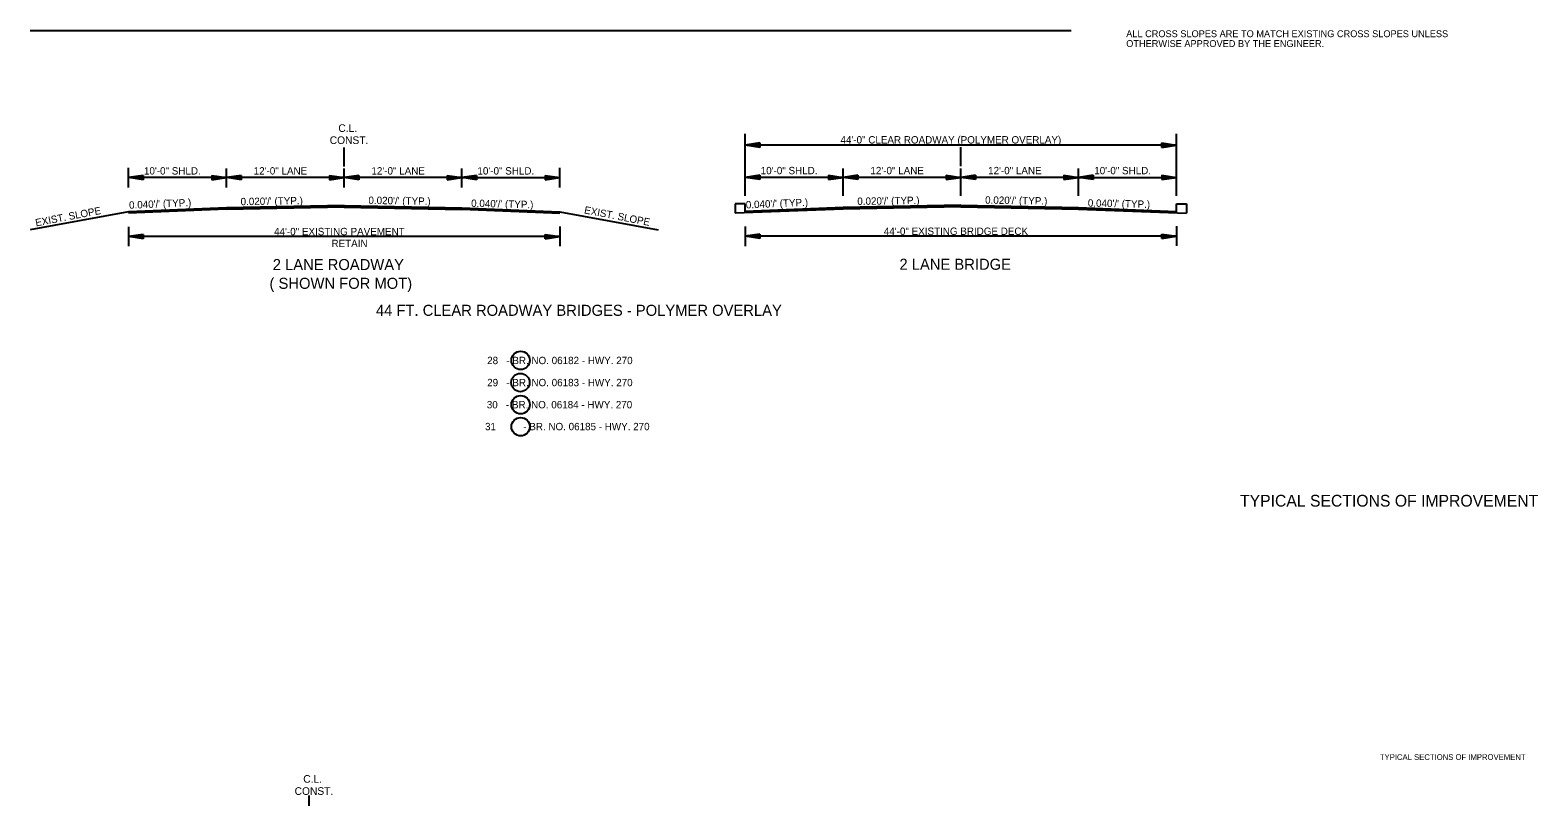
# Model space of a CAD drawing. Extents: x 550980 to 1930787, y -1972975 to 596640.
# Drawn here: x 551009 to 552546, y -1959487 to -1958697 of the extents above; entities that cross this region are included whole.
import ezdxf

# ---------------------------------------------------------------- set-up
doc = ezdxf.new("R2010")
doc.units = 0
for name, color, linetype in [('R_Border', 7, 'Continuous'), ('R_Border Notes', 7, 'Continuous'), ('R_Draft', 7, 'Continuous'), ('S_AREA_CALC', 7, 'Continuous')]:
    doc.layers.add(name, color=color, linetype=linetype)

msp = doc.modelspace()

# ---------------------------------------------------------------- linework, layer by layer
at = {"layer": 'R_Border'}
for p, q in [((551009, -1958697.2), (552070.2, -1958697.2)), ((551737.7, -1958873.9), (551727.5, -1958873.9)), ((551727.5, -1958873.9), (551727.5, -1958883.4)), ((551737.7, -1958882.7), (551737.7, -1958873.9)), ((552177.7, -1958882.7), (552177.7, -1958873.9)), ((552177.7, -1958873.9), (552187.9, -1958873.9)), ((552187.9, -1958873.9), (552187.8, -1958883.4))]:
    msp.add_line(p, q, dxfattribs=at)
for centre in [(551508.9, -1959033.2), (551508.7, -1959055.7), (551508.9, -1959078.3), (551508.9, -1959100.7)]:
    msp.add_circle(centre, 9.34, dxfattribs=at)
at = {"layer": 'R_Draft'}
for p, q in [((551737.7, -1958865.6), (551737.7, -1958802.5)), ((552177.7, -1958865.6), (552177.7, -1958802.5)), ((551329, -1958827.7), (551329, -1958816.3)), ((551752.7, -1958811.7), (551737.7, -1958814)), ((552177.7, -1958814), (551737.7, -1958814)), ((551752.7, -1958816.2), (551737.7, -1958814)), ((551752.7, -1958812.1), (551740.2, -1958814)), ((551752.7, -1958815.8), (551740.2, -1958814)), ((551752.7, -1958812.5), (551742.8, -1958814)), ((551752.7, -1958815.5), (551742.8, -1958814)), ((551752.7, -1958812.8), (551745.3, -1958814)), ((551752.7, -1958815.1), (551745.3, -1958814)), ((551752.7, -1958813.2), (551747.8, -1958814)), ((551752.7, -1958814.7), (551747.8, -1958814)), ((551752.7, -1958813.6), (551750.3, -1958814)), ((551752.7, -1958814.3), (551750.3, -1958814)), ((551752.7, -1958811.7), (551752.7, -1958816.2)), ((551957.7, -1958827.5), (551957.7, -1958816)), ((552162.7, -1958811.7), (552177.7, -1958814)), ((552162.7, -1958816.2), (552162.7, -1958811.7)), ((552162.7, -1958812.1), (552175.2, -1958814)), ((552162.7, -1958812.5), (552172.6, -1958814)), ((552162.7, -1958812.8), (552170.1, -1958814)), ((552162.7, -1958813.2), (552167.6, -1958814)), ((552162.7, -1958813.6), (552165.1, -1958814)), ((552162.7, -1958816.2), (552177.7, -1958814)), ((552162.7, -1958814.7), (552167.6, -1958814)), ((552162.7, -1958815.5), (552172.6, -1958814)), ((552162.7, -1958815.8), (552175.2, -1958814)), ((552162.7, -1958815.1), (552170.1, -1958814)), ((552162.7, -1958814.3), (552165.1, -1958814)), ((551109, -1958857), (551109, -1958837)), ((551209, -1958857), (551209, -1958837.9)), ((551329, -1958835.7), (551329, -1958827.7)), ((551329, -1958857), (551329, -1958837.9)), ((551449, -1958857), (551449, -1958837.9)), ((551549, -1958857), (551549, -1958837)), ((551837.7, -1958865.6), (551837.7, -1958837.6)), ((551957.7, -1958835.5), (551957.7, -1958827.5)), ((551957.7, -1958865.6), (551957.7, -1958837.6)), ((552077.7, -1958865.6), (552077.7, -1958837.6)), ((551124, -1958844.8), (551109, -1958847)), ((551209, -1958847), (551109, -1958847)), ((551124, -1958849.3), (551109, -1958847)), ((551124, -1958845.2), (551111.5, -1958847)), ((551124, -1958848.9), (551111.5, -1958847)), ((551124, -1958845.6), (551114, -1958847)), ((551124, -1958848.5), (551114, -1958847)), ((551124, -1958845.9), (551116.5, -1958847)), ((551124, -1958848.2), (551116.5, -1958847)), ((551124, -1958846.3), (551119.1, -1958847)), ((551124, -1958847.8), (551119.1, -1958847)), ((551124, -1958846.7), (551121.6, -1958847)), ((551124, -1958847.4), (551121.6, -1958847)), ((551124, -1958844.8), (551124, -1958849.3)), ((551194, -1958844.8), (551209, -1958847)), ((551194, -1958844.8), (551194, -1958849.3)), ((551194, -1958845.2), (551206.4, -1958847)), ((551194, -1958845.6), (551203.9, -1958847)), ((551194, -1958845.9), (551201.4, -1958847)), ((551194, -1958846.3), (551198.8, -1958847)), ((551194, -1958846.7), (551196.3, -1958847)), ((551194, -1958849.3), (551209, -1958847)), ((551194, -1958847.8), (551198.8, -1958847)), ((551194, -1958848.5), (551203.9, -1958847)), ((551194, -1958848.9), (551206.4, -1958847)), ((551194, -1958848.2), (551201.4, -1958847)), ((551194, -1958847.4), (551196.3, -1958847)), ((551224, -1958844.8), (551209, -1958847)), ((551329, -1958847), (551209, -1958847)), ((551224, -1958849.3), (551209, -1958847)), ((551224, -1958845.2), (551211.5, -1958847)), ((551224, -1958848.9), (551211.5, -1958847)), ((551224, -1958845.6), (551214, -1958847)), ((551224, -1958848.5), (551214, -1958847)), ((551224, -1958845.9), (551216.5, -1958847)), ((551224, -1958848.2), (551216.5, -1958847)), ((551224, -1958846.3), (551219.1, -1958847)), ((551224, -1958847.8), (551219.1, -1958847)), ((551224, -1958846.7), (551221.6, -1958847)), ((551224, -1958847.4), (551221.6, -1958847)), ((551224, -1958844.8), (551224, -1958849.3)), ((551314, -1958844.8), (551329, -1958847)), ((551314, -1958844.8), (551314, -1958849.3)), ((551314, -1958845.2), (551326.4, -1958847)), ((551314, -1958845.6), (551323.9, -1958847)), ((551314, -1958845.9), (551321.4, -1958847)), ((551314, -1958846.3), (551318.8, -1958847)), ((551314, -1958846.7), (551316.3, -1958847)), ((551314, -1958849.3), (551329, -1958847)), ((551314, -1958847.8), (551318.8, -1958847)), ((551314, -1958848.5), (551323.9, -1958847)), ((551314, -1958848.9), (551326.4, -1958847)), ((551314, -1958848.2), (551321.4, -1958847)), ((551314, -1958847.4), (551316.3, -1958847)), ((551344, -1958844.8), (551329, -1958847)), ((551449, -1958847), (551329, -1958847)), ((551344, -1958849.3), (551329, -1958847)), ((551344, -1958845.2), (551331.5, -1958847)), ((551344, -1958848.9), (551331.5, -1958847)), ((551344, -1958845.6), (551334, -1958847)), ((551344, -1958848.5), (551334, -1958847)), ((551344, -1958845.9), (551336.5, -1958847)), ((551344, -1958848.2), (551336.5, -1958847)), ((551344, -1958846.3), (551339.1, -1958847)), ((551344, -1958847.8), (551339.1, -1958847)), ((551344, -1958846.7), (551341.6, -1958847)), ((551344, -1958847.4), (551341.6, -1958847)), ((551344, -1958844.8), (551344, -1958849.3)), ((551434, -1958844.8), (551449, -1958847)), ((551434, -1958844.8), (551434, -1958849.3)), ((551434, -1958845.2), (551446.4, -1958847)), ((551434, -1958845.6), (551443.9, -1958847)), ((551434, -1958845.9), (551441.4, -1958847)), ((551434, -1958846.3), (551438.8, -1958847)), ((551434, -1958846.7), (551436.3, -1958847)), ((551434, -1958849.3), (551449, -1958847)), ((551434, -1958847.8), (551438.8, -1958847)), ((551434, -1958848.5), (551443.9, -1958847)), ((551434, -1958848.9), (551446.4, -1958847)), ((551434, -1958848.2), (551441.4, -1958847)), ((551434, -1958847.4), (551436.3, -1958847)), ((551464, -1958844.8), (551449, -1958847)), ((551449, -1958847), (551549, -1958847)), ((551464, -1958849.3), (551449, -1958847)), ((551464, -1958845.2), (551451.5, -1958847)), ((551464, -1958848.9), (551451.5, -1958847)), ((551464, -1958845.6), (551454, -1958847)), ((551464, -1958848.5), (551454, -1958847)), ((551464, -1958845.9), (551456.5, -1958847)), ((551464, -1958848.2), (551456.5, -1958847)), ((551464, -1958846.3), (551459.1, -1958847)), ((551464, -1958847.8), (551459.1, -1958847)), ((551464, -1958846.7), (551461.6, -1958847)), ((551464, -1958847.4), (551461.6, -1958847)), ((551464, -1958844.8), (551464, -1958849.3)), ((551534, -1958844.8), (551549, -1958847)), ((551534, -1958844.8), (551534, -1958849.3)), ((551534, -1958845.2), (551546.4, -1958847)), ((551534, -1958845.6), (551543.9, -1958847)), ((551534, -1958845.9), (551541.4, -1958847)), ((551534, -1958846.3), (551538.8, -1958847)), ((551534, -1958846.7), (551536.3, -1958847)), ((551534, -1958849.3), (551549, -1958847)), ((551534, -1958847.8), (551538.8, -1958847)), ((551534, -1958848.5), (551543.9, -1958847)), ((551534, -1958848.9), (551546.4, -1958847)), ((551534, -1958848.2), (551541.4, -1958847)), ((551534, -1958847.4), (551536.3, -1958847)), ((551752.7, -1958844.5), (551737.7, -1958846.8)), ((551837.7, -1958846.8), (551737.7, -1958846.8)), ((551752.7, -1958849), (551737.7, -1958846.8)), ((551752.7, -1958844.9), (551740.2, -1958846.8)), ((551752.7, -1958848.7), (551740.2, -1958846.8)), ((551752.7, -1958845.3), (551742.8, -1958846.8)), ((551752.7, -1958848.3), (551742.8, -1958846.8)), ((551752.7, -1958845.7), (551745.3, -1958846.8)), ((551752.7, -1958847.9), (551745.3, -1958846.8)), ((551752.7, -1958846.1), (551747.8, -1958846.8)), ((551752.7, -1958847.5), (551747.8, -1958846.8)), ((551752.7, -1958846.4), (551750.3, -1958846.8)), ((551752.7, -1958847.2), (551750.3, -1958846.8)), ((551752.7, -1958844.5), (551752.7, -1958849)), ((551822.7, -1958844.5), (551837.7, -1958846.8)), ((551822.7, -1958844.5), (551822.7, -1958849)), ((551822.7, -1958844.9), (551835.2, -1958846.8)), ((551822.7, -1958845.3), (551832.6, -1958846.8)), ((551822.7, -1958845.7), (551830.1, -1958846.8)), ((551822.7, -1958846.1), (551827.6, -1958846.8)), ((551822.7, -1958846.4), (551825.1, -1958846.8)), ((551822.7, -1958849), (551837.7, -1958846.8)), ((551822.7, -1958847.5), (551827.6, -1958846.8)), ((551822.7, -1958848.3), (551832.6, -1958846.8)), ((551822.7, -1958848.7), (551835.2, -1958846.8)), ((551822.7, -1958847.9), (551830.1, -1958846.8)), ((551822.7, -1958847.2), (551825.1, -1958846.8)), ((551852.7, -1958844.5), (551837.7, -1958846.8)), ((551957.7, -1958846.8), (551837.7, -1958846.8)), ((551852.7, -1958849), (551837.7, -1958846.8)), ((551852.7, -1958844.9), (551840.2, -1958846.8)), ((551852.7, -1958848.7), (551840.2, -1958846.8)), ((551852.7, -1958845.3), (551842.8, -1958846.8)), ((551852.7, -1958848.3), (551842.8, -1958846.8)), ((551852.7, -1958845.7), (551845.3, -1958846.8)), ((551852.7, -1958847.9), (551845.3, -1958846.8)), ((551852.7, -1958846.1), (551847.8, -1958846.8)), ((551852.7, -1958847.5), (551847.8, -1958846.8)), ((551852.7, -1958846.4), (551850.3, -1958846.8)), ((551852.7, -1958847.2), (551850.3, -1958846.8)), ((551852.7, -1958844.5), (551852.7, -1958849)), ((551942.7, -1958844.5), (551957.7, -1958846.8)), ((551942.7, -1958844.5), (551942.7, -1958849)), ((551942.7, -1958844.9), (551955.2, -1958846.8)), ((551942.7, -1958845.3), (551952.6, -1958846.8)), ((551942.7, -1958845.7), (551950.1, -1958846.8)), ((551942.7, -1958846.1), (551947.6, -1958846.8)), ((551942.7, -1958846.4), (551945.1, -1958846.8)), ((551942.7, -1958849), (551957.7, -1958846.8)), ((551942.7, -1958847.5), (551947.6, -1958846.8)), ((551942.7, -1958848.3), (551952.6, -1958846.8)), ((551942.7, -1958848.7), (551955.2, -1958846.8)), ((551942.7, -1958847.9), (551950.1, -1958846.8)), ((551942.7, -1958847.2), (551945.1, -1958846.8)), ((551972.7, -1958844.5), (551957.7, -1958846.8)), ((552077.7, -1958846.8), (551957.7, -1958846.8)), ((551972.7, -1958849), (551957.7, -1958846.8)), ((551972.7, -1958844.9), (551960.2, -1958846.8)), ((551972.7, -1958848.7), (551960.2, -1958846.8)), ((551972.7, -1958845.3), (551962.8, -1958846.8)), ((551972.7, -1958848.3), (551962.8, -1958846.8)), ((551972.7, -1958845.7), (551965.3, -1958846.8)), ((551972.7, -1958847.9), (551965.3, -1958846.8)), ((551972.7, -1958846.1), (551967.8, -1958846.8)), ((551972.7, -1958847.5), (551967.8, -1958846.8)), ((551972.7, -1958846.4), (551970.3, -1958846.8)), ((551972.7, -1958847.2), (551970.3, -1958846.8)), ((551972.7, -1958844.5), (551972.7, -1958849)), ((552062.7, -1958844.5), (552077.7, -1958846.8)), ((552062.7, -1958844.5), (552062.7, -1958849)), ((552062.7, -1958844.9), (552075.2, -1958846.8)), ((552062.7, -1958845.3), (552072.6, -1958846.8)), ((552062.7, -1958845.7), (552070.1, -1958846.8)), ((552062.7, -1958846.1), (552067.6, -1958846.8)), ((552062.7, -1958846.4), (552065.1, -1958846.8)), ((552062.7, -1958849), (552077.7, -1958846.8)), ((552062.7, -1958847.5), (552067.6, -1958846.8)), ((552062.7, -1958848.3), (552072.6, -1958846.8)), ((552062.7, -1958848.7), (552075.2, -1958846.8)), ((552062.7, -1958847.9), (552070.1, -1958846.8)), ((552062.7, -1958847.2), (552065.1, -1958846.8)), ((552092.7, -1958844.5), (552077.7, -1958846.8)), ((552077.7, -1958846.8), (552177.7, -1958846.8)), ((552092.7, -1958849), (552077.7, -1958846.8)), ((552092.7, -1958844.9), (552080.2, -1958846.8)), ((552092.7, -1958848.7), (552080.2, -1958846.8)), ((552092.7, -1958845.3), (552082.8, -1958846.8)), ((552092.7, -1958848.3), (552082.8, -1958846.8)), ((552092.7, -1958845.7), (552085.3, -1958846.8)), ((552092.7, -1958847.9), (552085.3, -1958846.8)), ((552092.7, -1958846.1), (552087.8, -1958846.8)), ((552092.7, -1958847.5), (552087.8, -1958846.8)), ((552092.7, -1958846.4), (552090.3, -1958846.8)), ((552092.7, -1958847.2), (552090.3, -1958846.8)), ((552092.7, -1958844.5), (552092.7, -1958849)), ((552162.7, -1958844.5), (552177.7, -1958846.8)), ((552162.7, -1958844.5), (552162.7, -1958849)), ((552162.7, -1958844.9), (552175.2, -1958846.8)), ((552162.7, -1958845.3), (552172.6, -1958846.8)), ((552162.7, -1958845.7), (552170.1, -1958846.8)), ((552162.7, -1958846.1), (552167.6, -1958846.8)), ((552162.7, -1958846.4), (552165.1, -1958846.8)), ((552162.7, -1958849), (552177.7, -1958846.8)), ((552162.7, -1958847.5), (552167.6, -1958846.8)), ((552162.7, -1958848.3), (552172.6, -1958846.8)), ((552162.7, -1958848.7), (552175.2, -1958846.8)), ((552162.7, -1958847.9), (552170.1, -1958846.8)), ((552162.7, -1958847.2), (552165.1, -1958846.8)), ((551109, -1958881.8), (551008.9, -1958900.1)), ((551209, -1958877.8), (551109, -1958881.8)), ((551209, -1958878.1), (551109, -1958882.1)), ((551209, -1958878.4), (551109, -1958882.4)), ((551209, -1958878.7), (551109, -1958882.7)), ((551209, -1958879), (551109, -1958883)), ((551209, -1958879.3), (551109, -1958883.3)), ((551329, -1958875.4), (551209, -1958877.8)), ((551329, -1958875.7), (551209, -1958878.1)), ((551329, -1958876), (551209, -1958878.4)), ((551329, -1958876.3), (551209, -1958878.7)), ((551329, -1958876.6), (551209, -1958879)), ((551329, -1958876.9), (551209, -1958879.3)), ((551329, -1958877), (551209, -1958879.4)), ((551329, -1958875.4), (551449, -1958877.8)), ((551329, -1958875.7), (551449, -1958878.1)), ((551329, -1958876), (551449, -1958878.4)), ((551329, -1958876.3), (551449, -1958878.7)), ((551329, -1958876.6), (551449, -1958879)), ((551329, -1958876.9), (551449, -1958879.3)), ((551329, -1958877), (551449, -1958879.4)), ((551449, -1958877.8), (551549, -1958881.8)), ((551449, -1958878.1), (551549, -1958882.1)), ((551449, -1958878.4), (551549, -1958882.4)), ((551449, -1958878.7), (551549, -1958882.7)), ((551449, -1958879), (551549, -1958883)), ((551449, -1958879.3), (551549, -1958883.3)), ((551549, -1958881.8), (551649, -1958900.1)), ((551837.7, -1958879), (551727.5, -1958883.4)), ((551837.7, -1958877.5), (551737.7, -1958881.5)), ((551837.7, -1958877.8), (551737.7, -1958881.8)), ((551837.7, -1958878.1), (551737.7, -1958882.1)), ((551837.7, -1958878.4), (551737.7, -1958882.4)), ((551837.7, -1958878.7), (551737.7, -1958882.7)), ((551957.7, -1958875.1), (551837.7, -1958877.5)), ((551957.7, -1958875.4), (551837.7, -1958877.8)), ((551957.7, -1958875.7), (551837.7, -1958878.1)), ((551957.7, -1958876), (551837.7, -1958878.4)), ((551957.7, -1958876.3), (551837.7, -1958878.7)), ((551957.7, -1958876.6), (551837.7, -1958879)), ((551957.7, -1958876.8), (551837.7, -1958879.2)), ((551957.7, -1958875.1), (552077.7, -1958877.5)), ((551957.7, -1958875.4), (552077.7, -1958877.8)), ((551957.7, -1958875.7), (552077.7, -1958878.1)), ((551957.7, -1958876), (552077.7, -1958878.4)), ((551957.7, -1958876.3), (552077.7, -1958878.7)), ((551957.7, -1958876.6), (552077.7, -1958879)), ((551957.7, -1958876.8), (552077.7, -1958879.2)), ((552077.7, -1958877.5), (552177.7, -1958881.5)), ((552077.7, -1958877.8), (552177.7, -1958881.8)), ((552077.7, -1958878.1), (552177.7, -1958882.1)), ((552077.7, -1958878.4), (552177.7, -1958882.4)), ((552077.7, -1958878.7), (552177.7, -1958882.7)), ((552077.7, -1958879), (552187.9, -1958883.4)), ((551109, -1958897), (551109, -1958917)), ((551549, -1958896.8), (551549, -1958916.8)), ((551737.7, -1958896.8), (551737.7, -1958916.8)), ((552177.7, -1958896.5), (552177.7, -1958916.5)), ((551124, -1958904.8), (551109, -1958907)), ((551124, -1958909.3), (551109, -1958907)), ((551549, -1958907), (551109, -1958907)), ((551124, -1958905.1), (551111.5, -1958907)), ((551124, -1958908.9), (551111.5, -1958907)), ((551124, -1958905.5), (551114, -1958907)), ((551124, -1958908.5), (551114, -1958907)), ((551124, -1958905.9), (551116.5, -1958907)), ((551124, -1958908.1), (551116.5, -1958907)), ((551124, -1958906.3), (551119.1, -1958907)), ((551124, -1958907.7), (551119.1, -1958907)), ((551124, -1958906.7), (551121.6, -1958907)), ((551124, -1958907.4), (551121.6, -1958907)), ((551124, -1958904.8), (551124, -1958909.3)), ((551534, -1958904.8), (551549, -1958907)), ((551534, -1958909.3), (551534, -1958904.8)), ((551534, -1958905.1), (551546.4, -1958907)), ((551534, -1958905.5), (551543.9, -1958907)), ((551534, -1958905.9), (551541.4, -1958907)), ((551534, -1958906.3), (551538.8, -1958907)), ((551534, -1958906.7), (551536.3, -1958907)), ((551534, -1958909.3), (551549, -1958907)), ((551534, -1958907.7), (551538.8, -1958907)), ((551534, -1958908.5), (551543.9, -1958907)), ((551534, -1958908.9), (551546.4, -1958907)), ((551534, -1958908.1), (551541.4, -1958907)), ((551534, -1958907.4), (551536.3, -1958907)), ((551752.7, -1958904.5), (551737.7, -1958906.8)), ((551752.7, -1958909), (551737.7, -1958906.8)), ((552177.7, -1958906.8), (551737.7, -1958906.8)), ((551752.7, -1958904.9), (551740.2, -1958906.8)), ((551752.7, -1958908.6), (551740.2, -1958906.8)), ((551752.7, -1958905.3), (551742.8, -1958906.8)), ((551752.7, -1958908.3), (551742.8, -1958906.8)), ((551752.7, -1958905.6), (551745.3, -1958906.8)), ((551752.7, -1958907.9), (551745.3, -1958906.8)), ((551752.7, -1958906), (551747.8, -1958906.8)), ((551752.7, -1958907.5), (551747.8, -1958906.8)), ((551752.7, -1958906.4), (551750.3, -1958906.8)), ((551752.7, -1958907.1), (551750.3, -1958906.8)), ((551752.7, -1958904.5), (551752.7, -1958909)), ((552162.7, -1958904.5), (552177.7, -1958906.8)), ((552162.7, -1958909), (552162.7, -1958904.5)), ((552162.7, -1958904.9), (552175.2, -1958906.8)), ((552162.7, -1958905.3), (552172.6, -1958906.8)), ((552162.7, -1958905.6), (552170.1, -1958906.8)), ((552162.7, -1958906), (552167.6, -1958906.8)), ((552162.7, -1958906.4), (552165.1, -1958906.8)), ((552162.7, -1958909), (552177.7, -1958906.8)), ((552162.7, -1958907.5), (552167.6, -1958906.8)), ((552162.7, -1958908.3), (552172.6, -1958906.8)), ((552162.7, -1958908.6), (552175.2, -1958906.8)), ((552162.7, -1958907.9), (552170.1, -1958906.8)), ((552162.7, -1958907.1), (552165.1, -1958906.8)), ((551293.2, -1959486.8), (551293.2, -1959476.4))]:
    msp.add_line(p, q, dxfattribs=at)

# ---------------------------------------------------------------- texts
at = {"layer": 'R_Border'}
msp.add_text('( SHOWN FOR MOT)', height=11.25, dxfattribs=at).set_placement((551252.9, -1958960.3))
msp.add_text('TYPICAL SECTIONS OF IMPROVEMENT', height=12, rotation=360, dxfattribs=at).set_placement((552242.3, -1959182.1))
at = {"layer": 'R_Border Notes'}
for s, p in [('ALL CROSS SLOPES ARE TO MATCH EXISTING CROSS SLOPES UNLESS ', (552126.3, -1958704)), ('OTHERWISE APPROVED BY THE ENGINEER.', (552126.3, -1958714))]:
    msp.add_text(s, height=7, dxfattribs=at).set_placement(p)
at = {"layer": 'R_Draft'}
for s, height, p in [('C.L.', 7.8, (551323.1, -1958800.5)), ('CONST.', 7.8, (551314.3, -1958812.8)), ('44\'-0" CLEAR ROADWAY (POLYMER OVERLAY)', 7.5, (551835, -1958812.3)), ('10\'-0" SHLD.', 7.5, (551124.9, -1958843.9)), ('12\'-0" LANE', 7.5, (551236.8, -1958843.9)), ('12\'-0" LANE', 7.5, (551356.8, -1958843.9)), ('10\'-0" SHLD.', 7.5, (551464.9, -1958843.9)), ('10\'-0" SHLD.', 7.5, (551753.7, -1958843.6)), ('12\'-0" LANE', 7.5, (551865.5, -1958843.6)), ('12\'-0" LANE', 7.5, (551985.5, -1958843.6)), ('10\'-0" SHLD.', 7.5, (552093.7, -1958843.6)), ('44\'-0" EXISTING PAVEMENT ', 7.5, (551257.6, -1958905.7)), ('44\'-0" EXISTING BRIDGE DECK', 7.5, (551879.2, -1958905.4)), ('RETAIN', 7.5, (551316.1, -1958917.8)), ('2 LANE ROADWAY', 11.25, (551256.2, -1958941.2)), ('2 LANE BRIDGE', 11.25, (551895.1, -1958940.9)), ('44 FT. CLEAR ROADWAY BRIDGES - POLYMER OVERLAY', 11.25, (551361.4, -1958987.8)), ('      28   - BR. NO. 06182 - HWY. 270', 7.5, (551458.1, -1959037)), ('      29   - BR. NO. 06183 - HWY. 270', 7.5, (551458.1, -1959059.5)), ('      30   - BR. NO. 06184 - HWY. 270', 7.5, (551457.7, -1959082)), ('       31          - BR. NO. 06185 - HWY. 270', 7.5, (551453.1, -1959104.3)), ('CONST.', 7.8, (551278.5, -1959475.7)), ('C.L.', 7.8, (551287.3, -1959463.3))]:
    msp.add_text(s, height=height, dxfattribs=at).set_placement(p)
for s, rotation, p in [("  0.040'/' (TYP.)", 2.448, (551104.3, -1958879)), ("0.020'/' (TYP.)", 0.9719, (551223.5, -1958875.2)), ("0.020'/' (TYP.)", 359.0281, (551353.7, -1958873.8)), ("0.040'/' (TYP.)", 358.6816, (551458.4, -1958876.8)), ("  0.040'/' (TYP.)", 2.448, (551733.1, -1958878.7)), ("0.020'/' (TYP.)", 0.9719, (551852.2, -1958874.9)), ("0.020'/' (TYP.)", 359.0281, (551982.4, -1958873.5)), ("0.040'/' (TYP.)", 358.6816, (552087.1, -1958876.5)), ('EXIST. SLOPE', 10.8829, (551014.9, -1958896.8)), ('EXIST. SLOPE', 349.1171, (551573.3, -1958883.4))]:
    msp.add_text(s, height=7.5, rotation=rotation, dxfattribs=at).set_placement(p)
at = {"layer": 'S_AREA_CALC'}
msp.add_text('TYPICAL SECTIONS OF IMPROVEMENT', height=5.862, rotation=360, dxfattribs=at).set_placement((552384.9, -1959440.1))

doc.saveas('drawing.dxf')
